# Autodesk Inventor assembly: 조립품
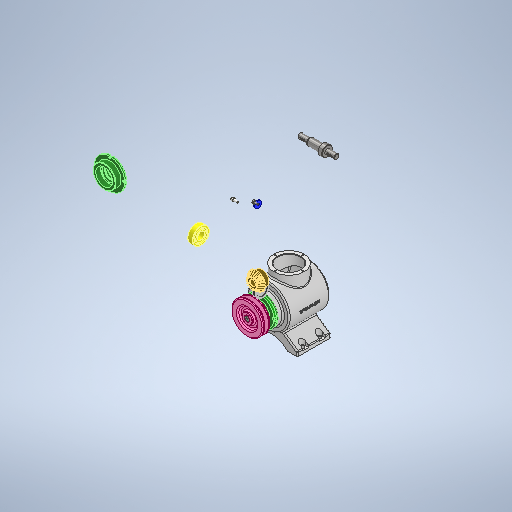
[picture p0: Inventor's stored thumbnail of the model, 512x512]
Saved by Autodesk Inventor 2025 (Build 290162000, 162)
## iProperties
Created: 2024-07
Part Number: 조립품
Document SubType Name: Assembly
Designer: 학생
Author: 학생
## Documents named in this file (15)
- C:\Users\학생\Desktop\740709V1003\조립품.iam
- C:\Users\학생\Desktop\석유림\0712 도면\01 20240518\공용부품_20240518_2\Ű 4 x 4 x 14\Ű 4 x 4 x 14.ipt
- C:\Users\학생\Desktop\석유림\0712 도면\01 20240518\공용부품_20240518_2\Ű 5 x 5 x 14\Ű 5 x 5 x 14.ipt
- C:\Users\학생\Desktop\석유림\0712 도면\01 20240518\공용부품_20240518_2\V-벨트풀리\V-벨트풀리.ipt
- C:\Users\학생\Desktop\석유림\0712 도면\01 20240518\공용부품_20240518_2\메인 베벨기어\메인 베벨기어.ipt
- C:\Users\학생\Desktop\석유림\0712 도면\01 20240518\공용부품_20240518_2\메인 축\메인 축.ipt
- C:\Users\학생\Desktop\석유림\0712 도면\01 20240518\공용부품_20240518_2\베어링 6203\베어링 6203.ipt
- C:\Users\학생\Desktop\석유림\0712 도면\01 20240518\공용부품_20240518_2\볼트 M4 x 10\볼트 M4 x 10.ipt
- C:\Users\학생\Desktop\석유림\0712 도면\01 20240518\공용부품_20240518_2\서브 베벨기어\서브 베벨기어.ipt
- C:\Users\학생\Desktop\석유림\0712 도면\01 20240518\공용부품_20240518_2\서브 축\서브 축.ipt
- C:\Users\학생\Desktop\석유림\0712 도면\01 20240518\공용부품_20240518_2\오일실 17 x 32 x 8\오일실 17 x 32 x 8.ipt
- C:\Users\학생\Desktop\석유림\0712 도면\01 20240518\공용부품_20240518_2\와셔 4 x 16\와셔 4 x 16.ipt
- C:\Users\학생\Desktop\석유림\0712 도면\01 20240518\공용부품_20240518_2\육각볼트 M4 x 8\육각볼트 M4 x 8.ipt
- C:\Users\학생\Desktop\석유림\0712 도면\01 20240518\공용부품_20240518_2\커버\커버.ipt
- C:\Users\학생\Desktop\740709V1003\본체.ipt
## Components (3 placed, 3 different names)
1. Ű 4 x 4 x 14:1 — 각도:1, 각도:2, 각도:3
2. Ű 5 x 5 x 14:1
3. V-벨트풀리:1
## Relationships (3: Angle 3)
- 각도:1 [Angle]: Ű 4 x 4 x 14:1
- 각도:2 [Angle]: Ű 4 x 4 x 14:1
- 각도:3 [Angle]: Ű 4 x 4 x 14:1
